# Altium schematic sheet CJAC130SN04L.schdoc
size 127 x 101 mm
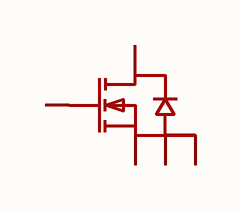
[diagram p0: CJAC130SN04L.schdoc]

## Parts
Q?  cjac130sn04l  [TDSON-8_L5.9-W5.2-P1.27-BL-1]  (value not drawn)

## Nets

Not connected (* = marked no-connect by the designer): Q? 1(S) 2(S) 3(S) 4(G) 5(D)

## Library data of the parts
Q? = cjac130sn04l: 数量:1个N沟道;漏源电压(Vdss):40V;连续漏极电流(Id):130A;导通电阻(RDS(on)):2mΩ@10V;耗散功率(Pd):120W;阈值电压(Vgs(th)):2V;; Manufacturer: CJ(江苏长电/长晶); AddInBom: yes; ModelId: 6d3ef2b64d5a4f2dbd2ee02e0c7053d2; ModelTransform: 205.511,242.1255,0,0,0,0,0,42.913,0; Number: 1个N沟道; Drain to Source Voltage: 40V; Current - Continuous Drain(Id): 130A; Pd - Power Dissipation: 120W; Gate Threshold Voltage (Vgs(th)): 2V; Gate Charge(Qg): 47.7nC@10V; Input Capacitance(Ciss): 2.62nF; Reverse Transfer Capacitance (Crss@Vds): 26pF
